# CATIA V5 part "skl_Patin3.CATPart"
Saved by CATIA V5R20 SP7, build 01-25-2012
Part number: skl_Patin3
Publications: "Axe_Patin3Patin2", "Axe_Patin3Equerre7", "Point.1", "Point.2", "Plan.1"
Bounding box of the stored display mesh (mm): x 0 to 20, y -47 to 0, z 22 to 111
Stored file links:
  J:\ACHTUNG2\skl_Patin3.CATPart
  J:\cmilovidofIAO\skl_IAO.CATProduct
  J:\ACHTUNG2\skl_IAO2.CATProduct
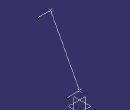
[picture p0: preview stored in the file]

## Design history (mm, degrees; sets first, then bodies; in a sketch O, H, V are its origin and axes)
Set1
  Point1: linked copy from another document
  Point2: linked copy from another document
  Plane1: linked copy from another document
Body1 (main body)
  Line1: type PtPt, FirstPoint Point1, SecondPoint Point2
  Line2: type Normal, RefPoint Point2, RefSkin Plane1, Start 0, End 20
  Line3: type PtDir, RefPoint Point1, Direction Plane1, Start 0, End 20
